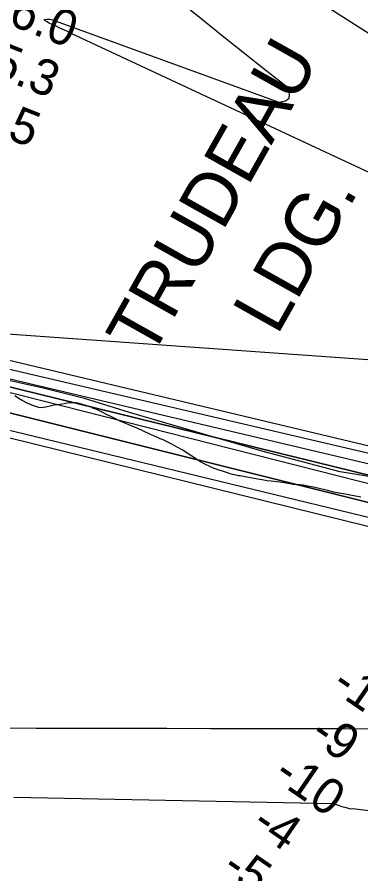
# Model space of a CAD drawing. Extents: x 3192986 to 3230865, y 867483 to 892886.
# Drawn here: x 3213255 to 3213899, y 878676 to 880283 of the extents above; entities that cross this region are included whole.
import ezdxf

# ---------------------------------------------------------------- set-up
doc = ezdxf.new("R2010")
doc.units = 0
for name, color, linetype in [('V-GRID-MAJR', 7, 'Continuous'), ('V-RIVR-EDGE', 7, 'Continuous'), ('V-RIVR-RANG', 7, 'Continuous'), ('V-SITE-VEGE', 7, 'Continuous'), ('V-TOPO-DPTH', 7, 'Continuous'), ('V-TOPO-GNAM-IDEN', 7, 'Continuous'), ('V-TOPO-MAJR', 7, 'Continuous'), ('V-TOPO-MINR', 7, 'Continuous'), ('V-TOPO-WATR', 7, 'Continuous')]:
    doc.layers.add(name, color=color, linetype=linetype)

msp = doc.modelspace()

# ---------------------------------------------------------------- linework, layer by layer
at = {"layer": 'V-GRID-MAJR'}
msp.add_spline([(3197200.8, 878983.5), (3202427.8, 878971.7), (3207654.8, 878960.7), (3212881.9, 878950.4), (3218108.9, 878940.9), (3223335.9, 878932.2), (3228562.9, 878924.2)], degree=3, dxfattribs=at)
at = {"layer": 'V-RIVR-EDGE'}
msp.add_lwpolyline([(3213936.8, 879418), (3213860.3, 879430.4), (3213716.1, 879468.6), (3213587.1, 879505.8), (3213465.5, 879541.4), (3213380.8, 879568.1), (3213303.5, 879587.4), (3213190.5, 879612)], dxfattribs=at)
at = {"layer": 'V-SITE-VEGE'}
for p, q in [((3213256.8, 879568.2), (3213250.4, 879572.6)), ((3213264.4, 879563.8), (3213256.8, 879568.2)), ((3213274.9, 879558.6), (3213264.4, 879563.8)), ((3213278.5, 879557.3), (3213274.9, 879558.6)), ((3213282.5, 879555.5), (3213278.5, 879557.3)), ((3213288, 879553.3), (3213282.5, 879555.5)), ((3213291.4, 879552.3), (3213288, 879553.3)), ((3213295.2, 879550.9), (3213291.4, 879552.3)), ((3213300.8, 879550.3), (3213295.2, 879550.9)), ((3213303.8, 879550.7), (3213300.8, 879550.3)), ((3213308.7, 879551.5), (3213303.8, 879550.7)), ((3213319.1, 879554.1), (3213308.7, 879551.5)), ((3213324.1, 879555.1), (3213319.1, 879554.1)), ((3213329.2, 879555.9), (3213324.1, 879555.1)), ((3213334.8, 879556.4), (3213329.2, 879555.9)), ((3213342.8, 879558), (3213334.8, 879556.4)), ((3213348.3, 879558.8), (3213342.8, 879558)), ((3213357.9, 879559.6), (3213348.3, 879558.8)), ((3213363.3, 879559.6), (3213357.9, 879559.6)), ((3213368.2, 879559), (3213363.3, 879559.6)), ((3213375.2, 879557.4), (3213368.2, 879559)), ((3213379.4, 879556.2), (3213375.2, 879557.4)), ((3213388.1, 879553.3), (3213379.4, 879556.2)), ((3213393.3, 879551.3), (3213388.1, 879553.3)), ((3213397.7, 879549.3), (3213393.3, 879551.3)), ((3213400.9, 879548.3), (3213397.7, 879549.3)), ((3213409.2, 879544.5), (3213400.9, 879548.3)), ((3213412.6, 879543.1), (3213409.2, 879544.5)), ((3213424.7, 879536.7), (3213412.6, 879543.1)), ((3213427.7, 879535.5), (3213424.7, 879536.7)), ((3213435.3, 879531.6), (3213427.7, 879535.5)), ((3213448, 879525.6), (3213435.3, 879531.6)), ((3213458.3, 879521), (3213448, 879525.6)), ((3213464.3, 879518.2), (3213458.3, 879521)), ((3213480.8, 879511.3), (3213464.3, 879518.2)), ((3213490.2, 879507.1), (3213480.8, 879511.3)), ((3213504.7, 879500.1), (3213490.2, 879507.1)), ((3213511.1, 879497.5), (3213504.7, 879500.1)), ((3213522.8, 879492.4), (3213511.1, 879497.5)), ((3213528.2, 879490.4), (3213522.8, 879492.4)), ((3213533.5, 879487.6), (3213528.2, 879490.4)), ((3213544.5, 879482.2), (3213533.5, 879487.6)), ((3213553.6, 879477.4), (3213544.5, 879482.2)), ((3213565.6, 879470.9), (3213553.6, 879477.4)), ((3213577.3, 879462.7), (3213565.6, 879470.9)), ((3213586.9, 879456.3), (3213577.3, 879462.7)), ((3213591.4, 879453.5), (3213586.9, 879456.3)), ((3213598.2, 879449.2), (3213591.4, 879453.5)), ((3213605.4, 879445.2), (3213598.2, 879449.2)), ((3213615.9, 879440), (3213605.4, 879445.2)), ((3213624.3, 879436.8), (3213615.9, 879440)), ((3213629.8, 879434.8), (3213624.3, 879436.8)), ((3213643.6, 879430.3), (3213629.8, 879434.8)), ((3213648.9, 879428.1), (3213643.6, 879430.3)), ((3213653.9, 879426.3), (3213648.9, 879428.1)), ((3213658.7, 879425.3), (3213653.9, 879426.3)), ((3213664.6, 879423.9), (3213658.7, 879425.3)), ((3213669.8, 879422.9), (3213664.6, 879423.9)), ((3213672.8, 879422.5), (3213669.8, 879422.9)), ((3213685.5, 879420.1), (3213672.8, 879422.5)), ((3213692.3, 879419.1), (3213685.5, 879420.1)), ((3213706, 879416.5), (3213692.3, 879419.1)), ((3213717, 879414.9), (3213706, 879416.5)), ((3213723.7, 879413.5), (3213717, 879414.9)), ((3213730.7, 879412.5), (3213723.7, 879413.5)), ((3213740.8, 879411.3), (3213730.7, 879412.5)), ((3213747.4, 879410.8), (3213740.8, 879411.3)), ((3213758.9, 879408.8), (3213747.4, 879410.8)), ((3213771.9, 879406.8), (3213758.9, 879408.8)), ((3213778.4, 879406.6), (3213771.9, 879406.8)), ((3213791, 879405), (3213778.4, 879406.6)), ((3213798.9, 879403.4), (3213791, 879405)), ((3213810.1, 879401.4), (3213798.9, 879403.4)), ((3213831.2, 879396.2), (3213810.1, 879401.4)), ((3213834.5, 879395.6), (3213831.2, 879396.2)), ((3213839.1, 879394.6), (3213834.5, 879395.6)), ((3213848.1, 879392.2), (3213839.1, 879394.6)), ((3213851.1, 879391.6), (3213848.1, 879392.2)), ((3213854.6, 879390.6), (3213851.1, 879391.6)), ((3213873.5, 879387.5), (3213854.6, 879390.6)), ((3213878.1, 879386.5), (3213873.5, 879387.5)), ((3213882.7, 879386.1), (3213878.1, 879386.5)), ((3213899, 879382.7), (3213882.7, 879386.1))]:
    msp.add_line(p, q, dxfattribs=at)
at = {"layer": 'V-TOPO-DPTH'}
for points in [[(3211584.9, 879955.4), (3212313.1, 879797.1), (3212317.1, 879796.2), (3212321.1, 879795.3), (3212325.1, 879794.3), (3212329.1, 879793.4), (3212333.8, 879792.2), (3212335.5, 879791.8), (3212337.1, 879791.4), (3212340.4, 879790.5), (3212390.9, 879777.4), (3212417.7, 879770.4), (3212444.6, 879763.1), (3212471.3, 879755.7), (3212498.1, 879748.1), (3212983.2, 879608.4), (3213013.9, 879599.4), (3213044.6, 879590), (3214143.1, 879315.3)], [(3214143.1, 879315.3), (3213044.6, 879590), (3213013.9, 879599.4), (3212983.2, 879608.4), (3212498.1, 879748.1), (3212471.3, 879755.7), (3212444.6, 879763.1), (3212417.7, 879770.4), (3212390.9, 879777.4), (3212340.4, 879790.5), (3212337.1, 879791.4), (3212335.5, 879791.8), (3212333.8, 879792.2), (3212329.1, 879793.4), (3212325.1, 879794.3), (3212321.1, 879795.3), (3212317.1, 879796.2), (3212313.1, 879797.1), (3211584.9, 879955.4)], [(3214130.7, 879413.8), (3213092.9, 879656.7), (3213073, 879662.5), (3213053.1, 879668.2), (3213033.2, 879673.8), (3212718.1, 879762.6), (3212658.1, 879779.4), (3212598.1, 879796.1), (3212538.1, 879812.5), (3212477.9, 879828.9), (3212380.6, 879855.1), (3212369.2, 879858.2), (3212357.7, 879861.3), (3212346.2, 879864.5), (3212334.8, 879867.7), (3212100.7, 879932.9), (3212018.6, 879954.3)], [(3212032, 879904.4), (3212085, 879893.1), (3212137.8, 879881.2), (3212190.5, 879868.5), (3212243, 879855.3), (3212307.6, 879838.5), (3212327.8, 879833.3), (3212347.9, 879828.1), (3212368, 879822.8), (3212388.2, 879817.6), (3212807.5, 879708.2), (3212850.1, 879696.8), (3212892.7, 879685), (3212935.1, 879672.7), (3212977.4, 879660), (3213051.6, 879637.2), (3213056.7, 879635.6), (3213061.8, 879634), (3213066.9, 879632.4), (3213072, 879630.7), (3214145.1, 879367.1)], [(3212032, 879904.4), (3212085, 879893.1), (3212137.8, 879881.2), (3212190.5, 879868.5), (3212243, 879855.3), (3212307.6, 879838.5), (3212327.8, 879833.3), (3212347.9, 879828.1), (3212368, 879822.8), (3212388.2, 879817.6), (3212807.5, 879708.2), (3212850.1, 879696.8), (3212892.7, 879685), (3212935.1, 879672.7), (3212977.4, 879660), (3213051.6, 879637.2), (3213056.7, 879635.6), (3213061.8, 879634), (3213066.9, 879632.4), (3213072, 879630.7), (3214145.1, 879367.1)], [(3214104.5, 879280.3), (3213045.3, 879541.3), (3213036.7, 879544.7), (3213028, 879548), (3213019.2, 879551), (3213010.4, 879553.9), (3212868.8, 879598.2), (3212788.9, 879622.3), (3212708.7, 879645.3), (3212628, 879666.6), (3212547.1, 879686.7), (3212370.8, 879728.7), (3212346.4, 879734.4), (3212322, 879740.1), (3212297.6, 879745.7), (3212273.2, 879751.3), (3211940.1, 879826.4)], [(3214104.5, 879280.3), (3213045.3, 879541.3), (3213036.7, 879544.7), (3213028, 879548), (3213019.2, 879551), (3213010.4, 879553.9), (3212868.8, 879598.2), (3212788.9, 879622.3), (3212708.7, 879645.3), (3212628, 879666.6), (3212547.1, 879686.7), (3212370.8, 879728.7), (3212346.4, 879734.4), (3212322, 879740.1), (3212297.6, 879745.7), (3212273.2, 879751.3), (3211940.1, 879826.4)], [(3213248.3, 878820.1), (3213848.8, 878808.1), (3213856.2, 878805.2), (3213863.6, 878802.6), (3213871.2, 878800.3), (3213878.8, 878798.2), (3213884.1, 878798.7), (3214784.1, 878685.7)], [(3213248.3, 878820.1), (3213848.8, 878808.1), (3213856.2, 878805.2), (3213863.6, 878802.6), (3213871.2, 878800.3), (3213878.8, 878798.2), (3213884.1, 878798.7), (3214784.1, 878685.7)]]:
    msp.add_lwpolyline(points, dxfattribs=at)
at = {"layer": 'V-TOPO-MAJR'}
for points in [[(3213434.6, 880558.7), (3214442.8, 879916.2)], [(3214394.1, 879767.7), (3213356.3, 880252.9), (3213349.2, 880256.3), (3213342, 880259.6), (3213334.8, 880262.9), (3213327.6, 880266.2), (3213315.8, 880271.6), (3213313.3, 880272.9), (3213310.8, 880274.4), (3213306.7, 880277), (3213306.4, 880277.2), (3213306, 880277.7), (3213305.9, 880278), (3213305.9, 880278.3), (3213305.9, 880278.5), (3213306.1, 880278.7), (3213306.3, 880278.8), (3213311.1, 880279.4), (3213316, 880279.5), (3213320.8, 880278.4), (3213745.3, 880123.8), (3213757.5, 880126.1), (3213764.9, 880131.1), (3213765.2, 880140), (3213760.8, 880151.6), (3213721.2, 880182.9), (3213681.7, 880214.3), (3213642.3, 880245.8), (3213602.9, 880277.5), (3213389.7, 880449.6)]]:
    msp.add_lwpolyline(points, dxfattribs=at)
at = {"layer": 'V-TOPO-MINR'}
for points in [[(3214176.9, 879416), (3213237.4, 879639.8), (3213229.5, 879640.4), (3213221.8, 879641.7), (3213214, 879643.5), (3213139.3, 879664.5), (3213109.8, 879672.7), (3213080.3, 879680.9), (3213050.8, 879689), (3213021.3, 879697.1), (3212494, 879840.1), (3212472, 879846), (3212450, 879852), (3212428, 879858), (3212406, 879864.1), (3212370, 879874), (3212366, 879875.1), (3212362.1, 879876.2), (3212358.1, 879877.3), (3212354.1, 879878.5), (3211585.8, 880029.7)], [(3214254.8, 879615.7), (3213104.2, 879697.8), (3213096.4, 879700), (3213088.6, 879702.1), (3213080.8, 879704.3), (3213073, 879706.5), (3212936.3, 879745.1), (3212860.1, 879766.8), (3212784.1, 879788.5), (3212708, 879810.6), (3212632.1, 879832.7), (3212396.7, 879901.7), (3212384.2, 879905.3), (3212371.7, 879908.9), (3212359.1, 879912.3), (3212346.5, 879915.7), (3212088.4, 879983.3), (3212025.2, 880000.1)], [(3214135.1, 879351.7), (3213059.3, 879624.8), (3213057.8, 879625.3), (3213057.3, 879625.4), (3213048.9, 879628.1), (3213044.2, 879629.5), (3213039.5, 879630.9), (3213034.7, 879632.2), (3213029.9, 879633.5), (3212364.8, 879804.4), (3212353.7, 879807.3), (3212342.6, 879810.1), (3212331.5, 879812.9), (3212320.4, 879815.7), (3212287.1, 879824.1), (3212259.3, 879830.9), (3212231.5, 879837.5), (3212203.5, 879843.8), (3212175.6, 879850), (3211590.9, 879974.6)], [(3214143.1, 879315.3), (3213044.6, 879590), (3213013.9, 879599.4), (3212983.2, 879608.4), (3212498.1, 879748.1), (3212471.3, 879755.7), (3212444.6, 879763.1), (3212417.7, 879770.4), (3212390.9, 879777.4), (3212340.4, 879790.5), (3212337.1, 879791.4), (3212335.5, 879791.8), (3212333.8, 879792.2), (3212329.1, 879793.4), (3212325.1, 879794.3), (3212321.1, 879795.3), (3212317.1, 879796.2), (3212313.1, 879797.1), (3211584.9, 879955.4)], [(3214130.7, 879413.8), (3213092.9, 879656.7), (3213073, 879662.5), (3213053.1, 879668.2), (3213033.2, 879673.8), (3212718.1, 879762.6), (3212658.1, 879779.4), (3212598.1, 879796.1), (3212538.1, 879812.5), (3212477.9, 879828.9), (3212380.6, 879855.1), (3212369.2, 879858.2), (3212357.7, 879861.3), (3212346.2, 879864.5), (3212334.8, 879867.7), (3212100.7, 879932.9), (3212018.6, 879954.3)], [(3214128.8, 879394), (3213090.1, 879639.6), (3213078.5, 879643.1), (3213066.8, 879646.7), (3213055.1, 879650.2), (3213043.5, 879653.7), (3212906.4, 879693.9), (3212826, 879717.2), (3212745.6, 879740), (3212664.9, 879762.2), (3212584.2, 879783.9), (3212392.1, 879834.8), (3212372.5, 879840), (3212352.9, 879845.2), (3212333.4, 879850.5), (3212313.8, 879855.7), (3212196.6, 879887.2), (3212118.2, 879907.4), (3212039.6, 879926.4), (3211960.5, 879943.7)], [(3214124.8, 879293.2), (3213064.3, 879550.3), (3213048.8, 879555.9), (3213033.2, 879561.3), (3213017.6, 879566.4), (3213001.9, 879571.4), (3212600.2, 879695.1), (3212555.5, 879708.4), (3212510.7, 879721.1), (3212465.6, 879733.1), (3212420.4, 879744.5), (3212404.9, 879748.2), (3212367.3, 879757.2), (3212329.7, 879766.1), (3212292, 879774.9), (3212254.4, 879783.6), (3211762.8, 879895.5)], [(3214104.5, 879280.3), (3213045.3, 879541.3), (3213036.7, 879544.7), (3213028, 879548), (3213019.2, 879551), (3213010.4, 879553.9), (3212868.8, 879598.2), (3212788.9, 879622.3), (3212708.7, 879645.3), (3212628, 879666.6), (3212547.1, 879686.7), (3212370.8, 879728.7), (3212346.4, 879734.4), (3212322, 879740.1), (3212297.6, 879745.7), (3212273.2, 879751.3), (3211940.1, 879826.4)], [(3213248.3, 878820.1), (3213848.8, 878808.1), (3213856.2, 878805.2), (3213863.6, 878802.6), (3213871.2, 878800.3), (3213878.8, 878798.2), (3213884.1, 878798.7), (3214784.1, 878685.7)]]:
    msp.add_lwpolyline(points, dxfattribs=at)
at = {"layer": 'V-TOPO-WATR'}
msp.add_lwpolyline([(3214145.1, 879367.1), (3213072, 879630.7), (3213066.9, 879632.4), (3213061.8, 879634), (3213056.7, 879635.6), (3213051.6, 879637.2), (3212977.4, 879660), (3212935.1, 879672.7), (3212892.7, 879685), (3212850.1, 879696.8), (3212807.5, 879708.2), (3212388.2, 879817.6), (3212368, 879822.8), (3212347.9, 879828.1), (3212327.8, 879833.3), (3212307.6, 879838.5), (3212243, 879855.3), (3212190.5, 879868.5), (3212137.8, 879881.2), (3212085, 879893.1), (3212032, 879904.4)], dxfattribs=at)

# ---------------------------------------------------------------- texts
at = {"layer": 'V-RIVR-RANG'}
for s, rotation, p in [('36.0', 338.3783, (3213188.9, 880289.1)), ('35.3', 338.3783, (3213155, 880195)), ('34.5', 338.3783, (3213118.3, 880102)), ('-15', 325.4449, (3213840.7, 879022.3)), ('-9', 325.4449, (3213800.2, 878928.8)), ('-10', 325.4449, (3213732.2, 878854.2)), ('-4', 325.4449, (3213691.1, 878761.2)), ('-5', 325.4449, (3213635, 878678.4))]:
    msp.add_text(s, height=67, rotation=rotation, dxfattribs=at).set_placement(p)
at = {"layer": 'V-TOPO-GNAM-IDEN'}
for s, p in [('TRUDEAU', (3213505.3, 879640.5)), ('LDG.', (3213742.3, 879684.5))]:
    msp.add_text(s, height=100, rotation=60.6596, dxfattribs=at).set_placement(p)

doc.saveas('drawing.dxf')
